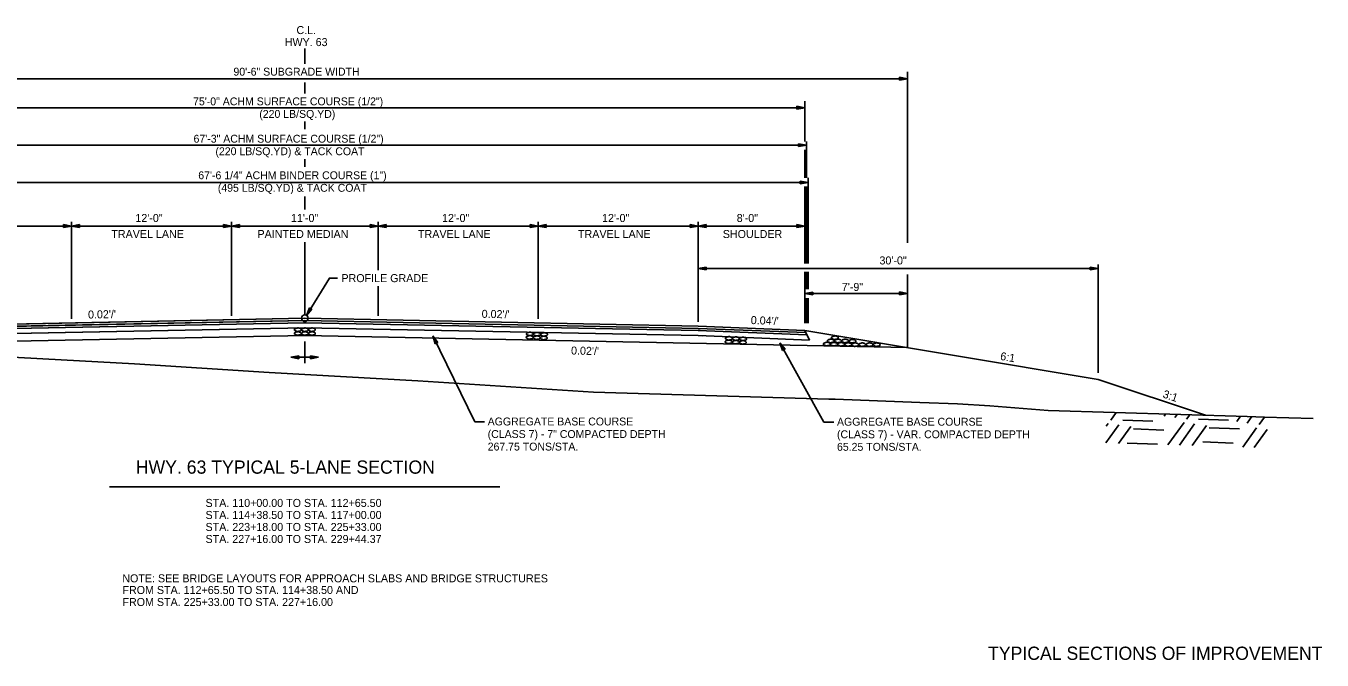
# Model space of a CAD drawing. Extents: x 1461846 to 1462006, y 1686171 to 1686805.
# Drawn here: x 1461905.3 to 1462002.5, y 1686703.4 to 1686750.9 of the extents above; entities that cross this region are included whole.
import ezdxf

# ---------------------------------------------------------------- set-up
doc = ezdxf.new("R2010")
doc.units = 0
for name, color, linetype in [('1', 7, 'Continuous'), ('10', 7, 'Continuous'), ('12', 7, 'Continuous'), ('19', 7, 'Continuous'), ('20', 7, 'Continuous'), ('3', 7, 'Continuous'), ('R_Draft', 7, 'Continuous')]:
    doc.layers.add(name, color=color, linetype=linetype)

# ---------------------------------------------------------------- blocks, each defined once
blk = doc.blocks.new('ROCKS')
at = {"layer": '1'}
blk.add_spline([(0.013, 0.06), (0.053, 0.053), (0.107, 0.033), (0.133, 0.013), (0.133, -0.007), (0.12, -0.033), (0.107, -0.04), (0.073, -0.053), (0.033, -0.067), (0.013, -0.067), (-0.02, -0.06), (-0.06, -0.053), (-0.087, -0.047), (-0.113, -0.02), (-0.113, -0.007), (-0.107, 0.02), (-0.087, 0.033), (-0.067, 0.047), (-0.033, 0.053), (-0.02, 0.06), (0.013, 0.06)], degree=3, dxfattribs=at)

msp = doc.modelspace()

# ---------------------------------------------------------------- linework, layer by layer
at = {"layer": '19'}
for p, q in [((1461880.979, 1686746.979), (1461971.391, 1686746.979)), ((1461970.791, 1686746.874), (1461970.791, 1686747.084)), ((1461970.791, 1686747.084), (1461971.391, 1686746.979)), ((1461970.791, 1686747.029), (1461971.231, 1686746.994)), ((1461971.391, 1686746.979), (1461970.791, 1686746.874)), ((1461971.231, 1686746.964), (1461970.791, 1686746.924)), ((1461971.391, 1686734.692), (1461971.391, 1686747.499)), ((1461963.075, 1686744.701), (1461963.075, 1686744.911)), ((1461963.075, 1686744.911), (1461963.675, 1686744.806)), ((1461963.075, 1686744.856), (1461963.515, 1686744.821)), ((1461963.675, 1686742.269), (1461963.675, 1686745.306)), ((1461888.675, 1686744.806), (1461963.675, 1686744.806)), ((1461963.675, 1686744.806), (1461963.075, 1686744.701)), ((1461963.515, 1686744.791), (1461963.075, 1686744.751)), ((1461963.675, 1686739.54), (1461963.675, 1686741.64)), ((1461963.675, 1686733.145), (1461963.675, 1686738.904)), ((1461963.675, 1686728.668), (1461963.675, 1686732.512)), ((1461971.391, 1686731.074), (1461971.391, 1686732.313)), ((1461971.391, 1686726.865), (1461971.391, 1686731.074)), ((1461938.923, 1686721.268), (1461935.789, 1686727.707)), ((1461935.965, 1686727.126), (1461935.789, 1686727.707)), ((1461935.789, 1686727.707), (1461936.152, 1686727.219)), ((1461936.009, 1686727.149), (1461935.846, 1686727.558)), ((1461935.871, 1686727.571), (1461936.104, 1686727.197)), ((1461963.675, 1686728.123), (1461964.036, 1686727.4)), ((1461964.036, 1686727.4), (1461963.845, 1686727.783)), ((1461963.845, 1686727.783), (1461963.845, 1686727.783)), ((1461964.036, 1686727.4), (1461964.036, 1686727.4)), ((1461936.152, 1686727.219), (1461935.965, 1686727.126)), ((1461965.122, 1686721.249), (1461961.802, 1686727.184)), ((1461962.017, 1686726.616), (1461961.802, 1686727.184)), ((1461961.802, 1686727.184), (1461962.198, 1686726.721)), ((1461962.06, 1686726.641), (1461961.869, 1686727.039)), ((1461961.894, 1686727.053), (1461962.15, 1686726.696)), ((1461962.198, 1686726.721), (1461962.017, 1686726.616)), ((1461986.636, 1686721.393), (1461987.046, 1686721.964)), ((1461990.633, 1686721.705), (1461990.744, 1686721.852)), ((1461991.425, 1686721.589), (1461991.598, 1686721.828)), ((1461992.317, 1686721.469), (1461992.553, 1686721.801)), ((1461996.077, 1686721.298), (1461996.351, 1686721.685)), ((1461996.869, 1686721.182), (1461997.216, 1686721.66)), ((1461997.761, 1686721.063), (1461998.159, 1686721.625)), ((1461939.66, 1686721.268), (1461938.923, 1686721.268)), ((1461965.859, 1686721.249), (1461965.122, 1686721.249)), ((1461986.267, 1686719.687), (1461987.235, 1686721.041)), ((1461986.283, 1686720.936), (1461986.443, 1686721.157)), ((1461987.221, 1686719.66), (1461988.127, 1686720.921)), ((1461987.526, 1686721.405), (1461989.784, 1686721.314)), ((1461988.346, 1686720.75), (1461990.604, 1686720.66)), ((1461990.919, 1686719.548), (1461992.124, 1686721.233)), ((1461991.774, 1686719.524), (1461992.915, 1686721.117)), ((1461992.729, 1686719.497), (1461993.807, 1686720.997)), ((1461993.205, 1686721.471), (1461995.464, 1686721.391)), ((1461994.015, 1686720.818), (1461996.285, 1686720.736)), ((1461996.527, 1686719.382), (1461997.568, 1686720.826)), ((1461997.381, 1686719.358), (1461998.36, 1686720.71)), ((1461987.86, 1686719.685), (1461990.13, 1686719.603)), ((1461993.541, 1686719.762), (1461995.799, 1686719.671))]:
    msp.add_line(p, q, dxfattribs=at)
for points in [[(1461888.59, 1686727.953), (1461896.675, 1686728.276), (1461926.175, 1686728.866), (1461955.675, 1686728.276), (1461963.76, 1686727.953), (1461963.675, 1686728.123), (1461955.675, 1686728.443), (1461926.175, 1686729.033), (1461896.675, 1686728.443), (1461888.675, 1686728.123)], [(1461896.505, 1686728.103), (1461896.674, 1686728.109), (1461926.174, 1686728.699), (1461955.674, 1686728.109), (1461963.845, 1686727.783), (1461963.76, 1686727.953), (1461955.674, 1686728.276), (1461926.174, 1686728.866), (1461896.674, 1686728.276), (1461896.59, 1686728.273)]]:
    msp.add_lwpolyline(points, close=True, dxfattribs=at)
for points in [[(1461896.313, 1686727.72), (1461896.675, 1686727.734), (1461926.175, 1686728.324), (1461955.675, 1686727.734), (1461964.036, 1686727.4)], [(1461963.845, 1686727.783), (1461955.675, 1686728.109), (1461926.175, 1686728.699), (1461896.675, 1686728.109), (1461896.505, 1686728.103)]]:
    msp.add_lwpolyline(points, dxfattribs=at)
at = {"layer": '20'}
for p, q in [((1461926.176, 1686743.192), (1461926.176, 1686743.761)), ((1461963.801, 1686742.006), (1461896.545, 1686742.006)), ((1461963.201, 1686741.901), (1461963.201, 1686742.111)), ((1461963.201, 1686742.111), (1461963.801, 1686742.006)), ((1461963.201, 1686742.056), (1461963.641, 1686742.021)), ((1461963.801, 1686742.006), (1461963.201, 1686741.901)), ((1461963.641, 1686741.991), (1461963.201, 1686741.951)), ((1461963.801, 1686739.54), (1461963.801, 1686742.269)), ((1461926.176, 1686740.374), (1461926.176, 1686740.943)), ((1461963.933, 1686739.206), (1461896.413, 1686739.206)), ((1461963.333, 1686739.101), (1461963.333, 1686739.311)), ((1461963.333, 1686739.311), (1461963.933, 1686739.206)), ((1461963.333, 1686739.256), (1461963.773, 1686739.221)), ((1461963.933, 1686739.206), (1461963.333, 1686739.101)), ((1461963.773, 1686739.191), (1461963.333, 1686739.151)), ((1461963.933, 1686733.367), (1461963.933, 1686739.54)), ((1461963.801, 1686733.145), (1461963.801, 1686738.904)), ((1461963.933, 1686733.145), (1461963.933, 1686733.367)), ((1461963.801, 1686731.201), (1461963.801, 1686732.512)), ((1461963.933, 1686731.201), (1461963.933, 1686732.512)), ((1461964.275, 1686730.998), (1461963.675, 1686730.894)), ((1461963.675, 1686730.894), (1461971.391, 1686730.894)), ((1461963.675, 1686730.894), (1461964.275, 1686730.788)), ((1461963.801, 1686728.668), (1461963.801, 1686730.534)), ((1461964.275, 1686730.943), (1461963.835, 1686730.908)), ((1461963.835, 1686730.878), (1461964.275, 1686730.838)), ((1461963.933, 1686728.668), (1461963.933, 1686730.534)), ((1461964.275, 1686730.788), (1461964.275, 1686730.998)), ((1461970.791, 1686730.999), (1461970.791, 1686730.789)), ((1461971.391, 1686730.894), (1461970.791, 1686730.999)), ((1461971.231, 1686730.909), (1461970.791, 1686730.944)), ((1461970.791, 1686730.789), (1461971.391, 1686730.894)), ((1461970.791, 1686730.839), (1461971.231, 1686730.879))]:
    msp.add_line(p, q, dxfattribs=at)
at = {"layer": '3'}
msp.add_line((1461911.527, 1686716.398), (1461940.822, 1686716.398), dxfattribs=at)
at = {"layer": 'R_Draft'}
for p, q in [((1461926.175, 1686748.093), (1461926.175, 1686749.237)), ((1461926.175, 1686745.874), (1461926.175, 1686746.706)), ((1461926.175, 1686737.178), (1461926.175, 1686738.165)), ((1461908.675, 1686728.983), (1461908.675, 1686736.243)), ((1461920.675, 1686729.223), (1461920.675, 1686736.243)), ((1461931.675, 1686732.638), (1461931.675, 1686736.243)), ((1461943.675, 1686728.983), (1461943.675, 1686736.243)), ((1461955.675, 1686728.772), (1461955.675, 1686736.243)), ((1461963.675, 1686733.145), (1461963.675, 1686736.243)), ((1461896.675, 1686735.943), (1461908.675, 1686735.943)), ((1461908.075, 1686736.048), (1461908.075, 1686735.838)), ((1461908.675, 1686735.943), (1461908.075, 1686736.048)), ((1461908.515, 1686735.958), (1461908.075, 1686735.993)), ((1461908.075, 1686735.838), (1461908.675, 1686735.943)), ((1461908.075, 1686735.888), (1461908.515, 1686735.928)), ((1461909.275, 1686736.048), (1461908.675, 1686735.943)), ((1461908.675, 1686735.943), (1461920.675, 1686735.943)), ((1461908.675, 1686735.943), (1461909.275, 1686735.838)), ((1461909.275, 1686735.993), (1461908.835, 1686735.958)), ((1461908.835, 1686735.928), (1461909.275, 1686735.888)), ((1461909.275, 1686735.838), (1461909.275, 1686736.048)), ((1461920.075, 1686736.048), (1461920.075, 1686735.838)), ((1461920.675, 1686735.943), (1461920.075, 1686736.048)), ((1461920.515, 1686735.958), (1461920.075, 1686735.993)), ((1461920.075, 1686735.838), (1461920.675, 1686735.943)), ((1461920.075, 1686735.888), (1461920.515, 1686735.928)), ((1461920.675, 1686735.943), (1461921.275, 1686736.048)), ((1461931.675, 1686735.943), (1461920.675, 1686735.943)), ((1461921.275, 1686735.838), (1461920.675, 1686735.943)), ((1461920.835, 1686735.958), (1461921.275, 1686735.993)), ((1461921.275, 1686735.888), (1461920.835, 1686735.928)), ((1461921.275, 1686736.048), (1461921.275, 1686735.838)), ((1461931.075, 1686735.838), (1461931.075, 1686736.048)), ((1461931.075, 1686736.048), (1461931.675, 1686735.943)), ((1461931.075, 1686735.993), (1461931.515, 1686735.958)), ((1461931.675, 1686735.943), (1461931.075, 1686735.838)), ((1461931.515, 1686735.928), (1461931.075, 1686735.888)), ((1461931.675, 1686735.943), (1461932.275, 1686736.048)), ((1461943.675, 1686735.943), (1461931.675, 1686735.943)), ((1461932.275, 1686735.838), (1461931.675, 1686735.943)), ((1461931.835, 1686735.958), (1461932.275, 1686735.993)), ((1461932.275, 1686735.888), (1461931.835, 1686735.928)), ((1461932.275, 1686736.048), (1461932.275, 1686735.838)), ((1461943.075, 1686735.838), (1461943.075, 1686736.048)), ((1461943.075, 1686736.048), (1461943.675, 1686735.943)), ((1461943.075, 1686735.993), (1461943.515, 1686735.958)), ((1461943.675, 1686735.943), (1461943.075, 1686735.838)), ((1461943.515, 1686735.928), (1461943.075, 1686735.888)), ((1461943.675, 1686735.943), (1461944.275, 1686736.048)), ((1461955.675, 1686735.943), (1461943.675, 1686735.943)), ((1461944.275, 1686735.838), (1461943.675, 1686735.943)), ((1461943.835, 1686735.958), (1461944.275, 1686735.993)), ((1461944.275, 1686735.888), (1461943.835, 1686735.928)), ((1461944.275, 1686736.048), (1461944.275, 1686735.838)), ((1461955.075, 1686735.838), (1461955.075, 1686736.048)), ((1461955.075, 1686736.048), (1461955.675, 1686735.943)), ((1461955.075, 1686735.838), (1461955.075, 1686736.048)), ((1461955.075, 1686736.048), (1461955.675, 1686735.943)), ((1461955.075, 1686735.838), (1461955.075, 1686736.048)), ((1461955.075, 1686736.048), (1461955.675, 1686735.943)), ((1461955.075, 1686735.993), (1461955.515, 1686735.958)), ((1461955.075, 1686735.993), (1461955.515, 1686735.958)), ((1461955.075, 1686735.993), (1461955.515, 1686735.958)), ((1461955.675, 1686735.943), (1461955.075, 1686735.838)), ((1461955.675, 1686735.943), (1461955.075, 1686735.838)), ((1461955.675, 1686735.943), (1461955.075, 1686735.838)), ((1461955.515, 1686735.928), (1461955.075, 1686735.888)), ((1461955.515, 1686735.928), (1461955.075, 1686735.888)), ((1461955.515, 1686735.928), (1461955.075, 1686735.888)), ((1461955.675, 1686735.943), (1461956.275, 1686736.048)), ((1461963.675, 1686735.943), (1461955.675, 1686735.943)), ((1461956.275, 1686735.838), (1461955.675, 1686735.943)), ((1461955.835, 1686735.958), (1461956.275, 1686735.993)), ((1461956.275, 1686735.888), (1461955.835, 1686735.928)), ((1461956.275, 1686736.048), (1461956.275, 1686735.838)), ((1461963.075, 1686735.838), (1461963.075, 1686736.048)), ((1461963.075, 1686736.048), (1461963.675, 1686735.943)), ((1461963.075, 1686735.993), (1461963.515, 1686735.958)), ((1461963.675, 1686735.943), (1461963.075, 1686735.838)), ((1461963.515, 1686735.928), (1461963.075, 1686735.888)), ((1461926.175, 1686729.28), (1461926.175, 1686734.743)), ((1461955.675, 1686732.764), (1461956.275, 1686732.869)), ((1461985.675, 1686732.764), (1461955.675, 1686732.764)), ((1461956.275, 1686732.659), (1461955.675, 1686732.764)), ((1461955.835, 1686732.779), (1461956.275, 1686732.814)), ((1461956.275, 1686732.709), (1461955.835, 1686732.749)), ((1461956.275, 1686732.869), (1461956.275, 1686732.659)), ((1461985.075, 1686732.659), (1461985.075, 1686732.869)), ((1461985.075, 1686732.869), (1461985.675, 1686732.764)), ((1461985.075, 1686732.814), (1461985.515, 1686732.779)), ((1461985.675, 1686732.764), (1461985.075, 1686732.659)), ((1461985.515, 1686732.749), (1461985.075, 1686732.709)), ((1461985.675, 1686724.952), (1461985.675, 1686733.064)), ((1461931.675, 1686729.223), (1461931.675, 1686731.438)), ((1461926.306, 1686729.246), (1461926.53, 1686729.812)), ((1461926.708, 1686729.703), (1461926.306, 1686729.246)), ((1461926.38, 1686729.387), (1461926.573, 1686729.78)), ((1461926.667, 1686729.724), (1461926.403, 1686729.375)), ((1461926.53, 1686729.812), (1461926.708, 1686729.703)), ((1461926.175, 1686729.033), (1461896.675, 1686728.443)), ((1461926.175, 1686728.866), (1461896.675, 1686728.276)), ((1461926.175, 1686728.699), (1461896.675, 1686728.109)), ((1461926.175, 1686728.324), (1461896.675, 1686727.734)), ((1461926.175, 1686729.033), (1461955.675, 1686728.443)), ((1461926.175, 1686728.866), (1461955.675, 1686728.276)), ((1461926.175, 1686728.699), (1461955.675, 1686728.109)), ((1461926.175, 1686728.324), (1461955.675, 1686727.734)), ((1461955.675, 1686728.443), (1461963.675, 1686728.123)), ((1461926.175, 1686727.741), (1461880.959, 1686726.837)), ((1461926.175, 1686727.741), (1461971.391, 1686726.837)), ((1461955.675, 1686728.276), (1461963.76, 1686727.953)), ((1461955.675, 1686728.109), (1461955.845, 1686728.103)), ((1461955.675, 1686728.109), (1461963.845, 1686727.783)), ((1461955.675, 1686727.734), (1461956.036, 1686727.72)), ((1461955.675, 1686727.734), (1461964.036, 1686727.4)), ((1461963.675, 1686728.123), (1461985.675, 1686724.456)), ((1461926.175, 1686727.289), (1461926.175, 1686725.657)), ((1461925.727, 1686726.214), (1461925.127, 1686726.109)), ((1461925.127, 1686726.109), (1461925.727, 1686726.004)), ((1461925.127, 1686726.109), (1461927.222, 1686726.109)), ((1461925.727, 1686726.159), (1461925.287, 1686726.124)), ((1461925.287, 1686726.094), (1461925.727, 1686726.054)), ((1461925.727, 1686726.004), (1461925.727, 1686726.214)), ((1461926.622, 1686726.004), (1461926.622, 1686726.214)), ((1461926.622, 1686726.214), (1461927.222, 1686726.109)), ((1461926.622, 1686726.159), (1461927.062, 1686726.124)), ((1461927.222, 1686726.109), (1461926.622, 1686726.004)), ((1461927.062, 1686726.094), (1461926.622, 1686726.054)), ((1461985.675, 1686724.456), (1461993.744, 1686721.766))]:
    msp.add_line(p, q, dxfattribs=at)
for points in [[(1461928.63, 1686732.038), (1461928.03, 1686732.037), (1461926.306, 1686729.246)], [(1461850.553, 1686728.595), (1461865.683, 1686728.014), (1461878.883, 1686727.333), (1461882.383, 1686727.222), (1461896.83, 1686726.446), (1461899.18, 1686726.39), (1461913.404, 1686725.61), (1461923.498, 1686724.971), (1461934.669, 1686724.333), (1461947.841, 1686723.499), (1461965.496, 1686722.968), (1461965.961, 1686722.96)], [(1461965.961, 1686722.96), (1461972.309, 1686722.71), (1461975.129, 1686722.612), (1461977.554, 1686722.466), (1461981.934, 1686722.115), (1461996.866, 1686721.674), (1461998.159, 1686721.625), (1462001.801, 1686721.515)]]:
    msp.add_lwpolyline(points, dxfattribs=at)
msp.add_circle((1461926.179, 1686729.03), 0.25, dxfattribs=at)

# ---------------------------------------------------------------- block references
at = {"layer": '19', "xscale": 2.061136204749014, "yscale": -2.061136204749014, "rotation": 180}
for p in [(1461925.675, 1686728.182), (1461926.206, 1686728.182), (1461926.728, 1686728.182), (1461925.675, 1686727.899), (1461926.206, 1686727.899), (1461926.739, 1686727.899), (1461943.069, 1686727.604), (1461943.086, 1686727.866), (1461943.599, 1686727.585), (1461943.616, 1686727.847), (1461944.127, 1686727.566), (1461944.144, 1686727.827), (1461957.99, 1686727.269), (1461958.007, 1686727.53), (1461958.519, 1686727.25), (1461958.536, 1686727.511), (1461959.048, 1686727.231), (1461959.065, 1686727.492), (1461965.655, 1686727.34), (1461965.96, 1686727.579), (1461966.197, 1686727.34), (1461966.731, 1686727.34), (1461967.274, 1686727.324), (1461965.348, 1686727.107), (1461965.892, 1686727.098), (1461966.426, 1686727.088), (1461966.95, 1686727.075), (1461967.481, 1686727.061), (1461968.008, 1686727.061), (1461968.552, 1686727.061), (1461969.09, 1686727.061)]:
    msp.add_blockref('ROCKS', p, dxfattribs=at)

# ---------------------------------------------------------------- texts
at = {"layer": '10'}
for s, p in [('STA. 110+00.00 TO STA. 112+65.50', (1461918.738, 1686714.898)), ('STA. 114+38.50 TO STA. 117+00.00', (1461918.738, 1686713.998)), ('STA. 223+18.00 TO STA. 225+33.00', (1461918.738, 1686713.098)), ('STA. 227+16.00 TO STA. 229+44.37', (1461918.738, 1686712.198)), ('FROM STA. 112+65.50 TO STA. 114+38.50 AND', (1461912.507, 1686708.376)), ('FROM STA. 225+33.00 TO STA. 227+16.00', (1461912.507, 1686707.476))]:
    msp.add_text(s, height=0.6, rotation=359.99538, dxfattribs=at).set_placement(p)
msp.add_text('NOTE: SEE BRIDGE LAYOUTS FOR APPROACH SLABS AND BRIDGE STRUCTURES', height=0.6, dxfattribs=at).set_placement((1461912.497, 1686709.248))
at = {"layer": '12'}
msp.add_text('HWY. 63 TYPICAL 5-LANE SECTION', height=0.98999, rotation=359.99538, dxfattribs=at).set_placement((1461913.504, 1686717.387))
at = {"layer": '19'}
for s, p in [('90\'-6" SUBGRADE WIDTH', (1461920.832, 1686747.209)), ('75\'-0" ACHM SURFACE COURSE (1/2")', (1461917.803, 1686744.984)), ('(220 LB/SQ.YD)', (1461922.769, 1686744.044))]:
    msp.add_text(s, height=0.59001, dxfattribs=at).set_placement(p)
for s, height, p in [('67\'-3" ACHM SURFACE COURSE (1/2")', 0.59001, (1461917.839, 1686742.188)), ('(220 LB/SQ.YD) & TACK COAT', 0.59001, (1461919.481, 1686741.248)), ('67\'-6 1/4" ACHM BINDER COURSE (1")', 0.59001, (1461918.194, 1686739.448)), ('(495 LB/SQ.YD) & TACK COAT', 0.59001, (1461919.66, 1686738.508)), ('AGGREGATE BASE COURSE', 0.59001, (1461939.899, 1686721.003)), ('AGGREGATE BASE COURSE', 0.59001, (1461966.097, 1686720.984)), ('(CLASS 7) - 7" COMPACTED DEPTH', 0.59001, (1461939.899, 1686720.063)), ('(CLASS 7) - VAR. COMPACTED DEPTH', 0.59001, (1461966.097, 1686720.044)), ('267.75 TONS/STA.', 0.59001, (1461939.899, 1686719.123)), ('65.25 TONS/STA.', 0.59001, (1461966.097, 1686719.104)), ('TYPICAL SECTIONS OF IMPROVEMENT', 0.98999, (1461977.425, 1686703.441))]:
    msp.add_text(s, height=height, rotation=360, dxfattribs=at).set_placement(p)
at = {"layer": 'R_Draft'}
for s, rotation, p in [('C.L.', 360, (1461925.558, 1686750.321)), ('HWY. 63', 360, (1461924.679, 1686749.421)), ('12\'-0"', 360, (1461913.477, 1686736.243)), ('TRAVEL LANE', 360, (1461911.675, 1686735.043)), ('PROFILE GRADE', 360, (1461928.93, 1686731.738)), ('7\'-9"', 360, (1461966.458, 1686731.076)), ("0.02'/'", 1.14576, (1461909.931, 1686729.008)), ("0.02'/'", 358.85424, (1461939.443, 1686729.067)), ("0.04'/'", 357.70939, (1461959.62, 1686728.602)), ("0.02'/'", 358.85424, (1461946.147, 1686726.316)), ('6:1', 350.53768, (1461978.308, 1686725.916)), ('3:1', 341.56505, (1461990.482, 1686723.11))]:
    msp.add_text(s, height=0.6, rotation=rotation, dxfattribs=at).set_placement(p)
for s, p in [('11\'-0"', (1461925.147, 1686736.243)), ('12\'-0"', (1461936.477, 1686736.243)), ('12\'-0"', (1461948.477, 1686736.243)), ('8\'-0"', (1461958.576, 1686736.243)), ('PAINTED MEDIAN', (1461922.634, 1686735.043)), ('TRAVEL LANE', (1461934.675, 1686735.043)), ('TRAVEL LANE', (1461946.675, 1686735.043)), ('SHOULDER', (1461957.532, 1686735.043)), ('30\'-0"', (1461969.283, 1686733.064))]:
    msp.add_text(s, height=0.6, dxfattribs=at).set_placement(p)

doc.saveas('drawing.dxf')
